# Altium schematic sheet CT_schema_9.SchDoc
size 388 x 278 mm
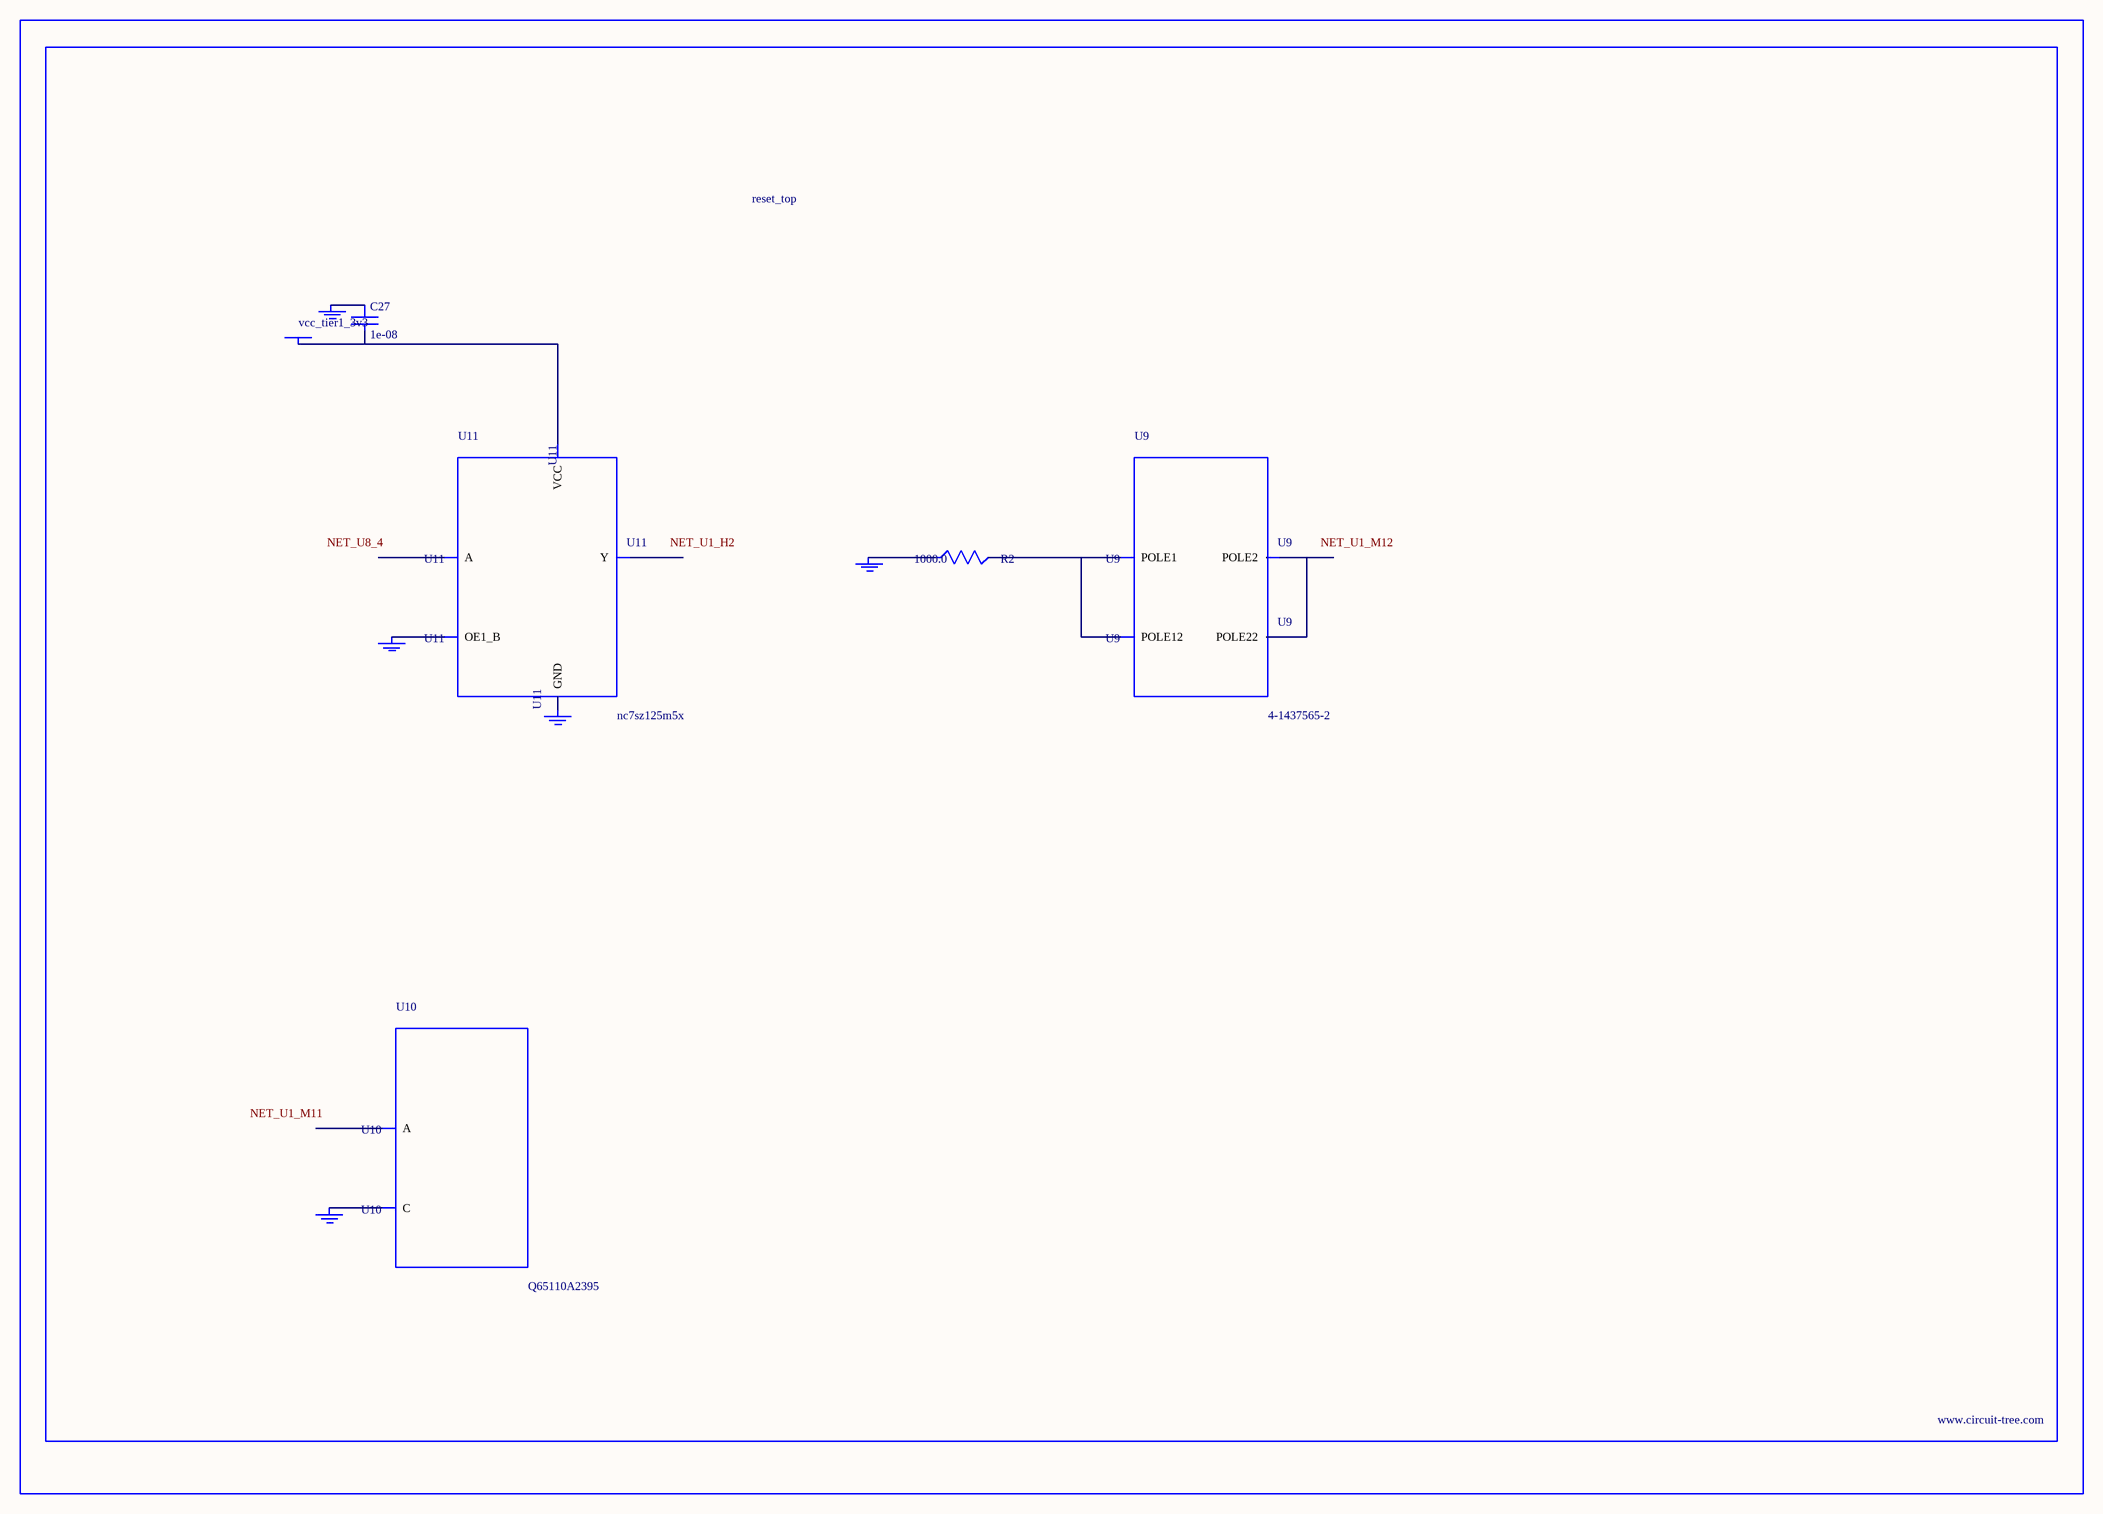
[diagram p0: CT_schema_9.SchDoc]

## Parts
BORDER8  (no value)
C27  1e-08  [C0402]
GND_INSTANCE_8_0  (no value)
GND_INSTANCE_8_1  (no value)
GND_INSTANCE_8_2  (no value)
GND_INSTANCE_8_3  (no value)
GND_INSTANCE_8_4  (no value)
POWER_INSTANCE_8_0  vcc_tier1_3v3
R2  1000.0  [R0603]
U9  4-1437565-2  [SW_4-1437565-2]
U10  Q65110A2395  [LGM67K-G1J2-24-Z]
U11  nc7sz125m5x  [NC7SZ125M5X]

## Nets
NetC27_1: C27.1 GND_INSTANCE_8_2.0(GND)
NetC27_2: C27.2 POWER_INSTANCE_8_0.0(PWR) U11.5(VCC)
NetGND_INSTANCE_8_0_0: GND_INSTANCE_8_0.0(GND) R2.1
NetGND_INSTANCE_8_1_0: GND_INSTANCE_8_1.0(GND) U10.C
NetGND_INSTANCE_8_3_0: GND_INSTANCE_8_3.0(GND) U11.1(OE1_B)
NetGND_INSTANCE_8_4_0: GND_INSTANCE_8_4.0(GND) U11.3(GND)
NetR2_2: R2.2 U9.1(POLE1) U9.2(POLE12)
NetU9_3: U9.3(POLE2) U9.4(POLE22)

Not connected (* = marked no-connect by the designer): U10 A; U11 2(A) 4(Y)

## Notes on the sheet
- Labels drawn without touching a wire or pin: NET_U1_H2, NET_U1_M11, NET_U1_M12, NET_U8_4

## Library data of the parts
BORDER8 = BORDER_PAGE8
C27 = C0402C103K3RAC
GND_INSTANCE_8_0-GND_INSTANCE_8_4 = GND
POWER_INSTANCE_8_0 = PWR
R2 = RC0603JR-071KL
